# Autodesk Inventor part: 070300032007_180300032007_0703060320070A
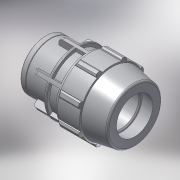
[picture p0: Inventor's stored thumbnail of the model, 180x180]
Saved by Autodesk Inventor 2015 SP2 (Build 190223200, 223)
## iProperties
Created: 2017-02
Part Number: 070300032007_180300032007_0703060320070A
Material: PVC-Piping
Description: PLASSON FEMALE ADAPTOR 32-3/4"
Document SubType Name: Modeling
Designer: KIM
Mass: 92.6774 g
Surface Area: 199.44 cm^2
Volume: 66.1981 cm^3
Density: 1.4 g/cm^3
Appearance: Smooth - White
Author: KIM
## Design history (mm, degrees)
derived "07030.ipt"
feature "Solid1::07030.ipt"
tag "TaggingFeature1"
body "Solid1"
other parameters: "d2" = 32, "d4" = 13.42857, "d5" = 23.5, "d7" = 64, "d9" = 13.42857, "d11" = 2.68571, "d12" = 51.2, "d13" = 120 deg, "d14" = 48, "d15" = 10 deg, "d16" = 57.6, "d18" = 1.6, "d19" = 35 deg, "d20" = 17.5 deg, "d21" = 59.52, "d23" = 0, "d25" = 360 deg, "d27" = 1.28, "d34" = 3.2, "d35" = 28.2, "d36" = 0, "d42" = 23.5, "d43" = 1.92, "d46" = 0.96, "d49" = 73, "d51" = 94, "d53" = 0.64, "d55" = 360 deg, "d61" = 19, "d62" = 25.6, "d63" = 24.117, "d64" = 31.33333, "d65" = 3.2, "d66" = 0.5, "d67" = 1, "d68" = 5.7, "d69" = 46.08, "d70" = 1.6, "d_" = 32, "E_" = 64, "H_" = 94, "l_" = 73, "l_2" = 19, "Rp_" = 24.117
